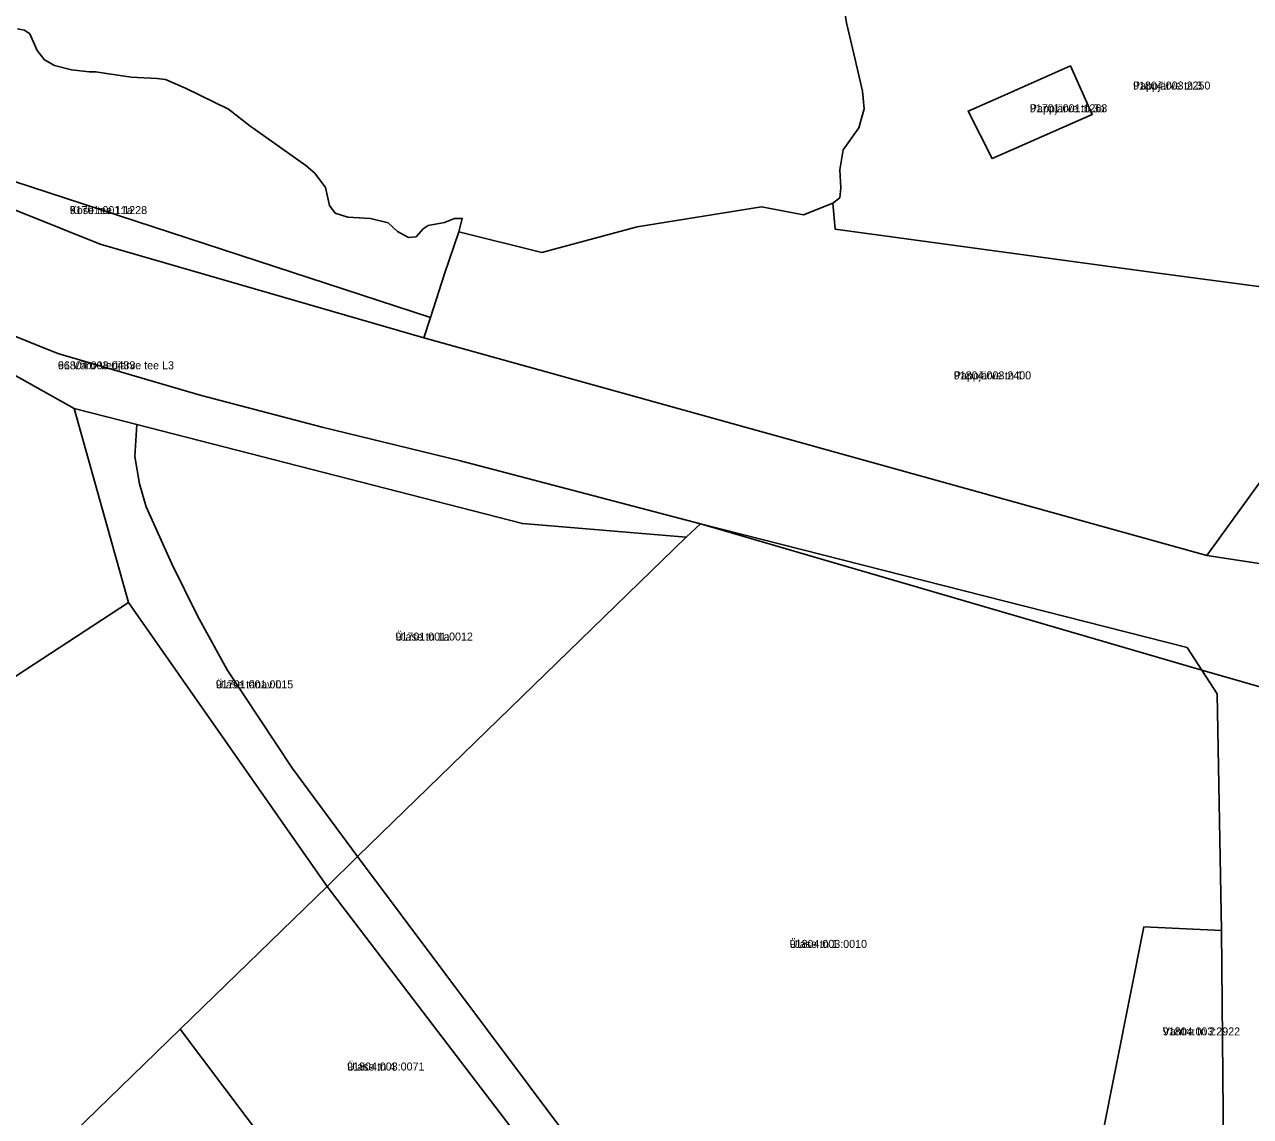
# Model space of a CAD drawing. Extents: x 655954 to 711923, y 6395079 to 6429745.
# Drawn here: x 680115.5 to 680345.2, y 6412086.7 to 6412291.4 of the extents above; entities that cross this region are included whole.
import ezdxf

# ---------------------------------------------------------------- set-up
doc = ezdxf.new("R2010")
doc.units = 0
for name, color, linetype in [('L_AADRESS', 7, 'Continuous'), ('PIIR', 7, 'Continuous'), ('TUNNUS', 7, 'Continuous')]:
    doc.layers.add(name, color=color, linetype=linetype)

msp = doc.modelspace()

# ---------------------------------------------------------------- linework, layer by layer
at = {"layer": 'PIIR'}
for points in [[(680270.91, 6412285.97), (680269.56, 6412291.77), (680268.21, 6412300.15), (680272.04, 6412300.46), (680309.99, 6412309.75), (680357.48, 6412321.49), (680370.12, 6412288.02), (680379.49, 6412257.67), (680371.24, 6412239.08), (680328.42, 6412244.77), (680267.41, 6412253.09), (680266.95, 6412257.92), (680268.29, 6412258.95), (680268.5, 6412260.8), (680268.26, 6412264.21), (680268.94, 6412267.94), (680271.87, 6412272.08), (680272.87, 6412275.64), (680272.53, 6412278.95)], [(680311.51, 6412283.68), (680296.9, 6412277.22), (680292.32, 6412275.21), (680296.81, 6412266.3), (680301.38, 6412268.31), (680315.56, 6412274.55)], [(680301.38, 6412268.31), (680296.81, 6412266.3), (680292.32, 6412275.21), (680296.9, 6412277.22), (680311.51, 6412283.68), (680315.56, 6412274.55)], [(680191.57, 6412236.5), (680190.32, 6412232.69), (680129.68, 6412250.27), (680106.42, 6412259.59), (680061.38, 6412279.1)], [(680057.47, 6412258.31), (680098.7, 6412238.99), (680121.74, 6412229.75), (680148.41, 6412221.98), (680171.26, 6412215.95), (680196.94, 6412209.71), (680242.17, 6412197.84), (680239.51, 6412195.3), (680208.82, 6412197.87), (680136.58, 6412216.43), (680124.79, 6412219.45), (680094.21, 6412236.6), (680073.54, 6412243.96), (680059.62, 6412250.38), (680048.66, 6412251.49)], [(680266.95, 6412257.92), (680267.41, 6412253.09), (680328.42, 6412244.77), (680371.24, 6412239.08), (680337.05, 6412191.89), (680190.32, 6412232.69), (680191.57, 6412236.5), (680194.23, 6412244.67), (680196.86, 6412252.6), (680212.46, 6412248.67), (680230.28, 6412253.54), (680253.6, 6412257.24), (680261.5, 6412255.76)], [(680029.07, 6412236.31), (680048.66, 6412251.49), (680059.62, 6412250.38), (680073.54, 6412243.96), (680094.21, 6412236.6), (680124.79, 6412219.45), (680135.01, 6412183.06), (680113.87, 6412169.29), (680093.78, 6412171.48), (680064.98, 6412158.77), (680062.91, 6412162.64), (680053.42, 6412181.06)], [(680135.01, 6412183.06), (680124.79, 6412219.45), (680136.58, 6412216.43), (680136.18, 6412210.48), (680137.05, 6412205.33), (680138.32, 6412201.02), (680143.13, 6412190.34), (680147.92, 6412180.6), (680153.46, 6412170.43), (680165.75, 6412151.95), (680177.93, 6412135.44), (680172.23, 6412129.84)], [(680136.18, 6412210.48), (680136.58, 6412216.43), (680208.82, 6412197.87), (680239.51, 6412195.3), (680177.93, 6412135.44), (680165.75, 6412151.95), (680153.46, 6412170.43), (680147.92, 6412180.6), (680143.13, 6412190.34), (680138.32, 6412201.02), (680137.05, 6412205.33)], [(680339.82, 6412121.56), (680325.23, 6412122.25), (680317.41, 6412082.68), (680305.27, 6412069.8), (680258.89, 6412067.74), (680264.48, 6412045.39), (680249.85, 6412039.28), (680177.93, 6412135.44), (680239.51, 6412195.3), (680242.17, 6412197.84), (680333.36, 6412174.63), (680338.98, 6412165.98)], [(680113.87, 6412169.29), (680135.01, 6412183.06), (680172.23, 6412129.84), (680144.65, 6412103.09), (680064.61, 6412025.27), (680029.16, 6412146.93), (680058.94, 6412160.44), (680062.91, 6412162.64), (680064.98, 6412158.77), (680093.78, 6412171.48)], [(680172.23, 6412129.84), (680207.25, 6412083.9), (680187.81, 6412068.25), (680179.6, 6412065.22), (680174.78, 6412065.85), (680169.78, 6412069.7), (680144.65, 6412103.09)], [(680325.23, 6412122.25), (680339.82, 6412121.56), (680340.18, 6412080.79), (680317.41, 6412082.68)], [(680144.65, 6412103.09), (680169.78, 6412069.7), (680174.78, 6412065.85), (680179.6, 6412065.22), (680187.81, 6412068.25), (680207.25, 6412083.9), (680216.28, 6412071.48), (680204.78, 6412056.18), (680218.04, 6412026.59), (680239.92, 6411995.28), (680256.59, 6412011.64), (680268.49, 6412001.99), (680151.27, 6411895.77), (680144.01, 6411889.12), (680137, 6411900.49), (680128.05, 6411895.16), (680136.21, 6411882.06), (680114.51, 6411862.4), (680110.62, 6411858.88), (680064.61, 6412025.27)]]:
    msp.add_lwpolyline(points, close=True, dxfattribs=at)
for points in [[(680372.55, 6412294.06), (680377.69, 6412279.06), (680382.91, 6412264.69), (680386, 6412255.23), (680385.97, 6412250.53), (680379.93, 6412239.55), (680347.28, 6412190.34), (680337.05, 6412191.89), (680371.24, 6412239.08), (680379.49, 6412257.67), (680370.12, 6412288.02), (680357.48, 6412321.49)], [(680269.56, 6412291.77), (680270.91, 6412285.97), (680272.53, 6412278.95), (680272.87, 6412275.64), (680271.87, 6412272.08), (680268.94, 6412267.94), (680268.26, 6412264.21), (680268.5, 6412260.8), (680268.29, 6412258.95), (680266.95, 6412257.92), (680261.5, 6412255.76), (680253.6, 6412257.24), (680230.28, 6412253.54), (680212.46, 6412248.67), (680196.86, 6412252.6), (680197.53, 6412255.1), (680196.1, 6412255.05), (680194.18, 6412254.32), (680191.13, 6412253.79), (680190.18, 6412253.13), (680188.87, 6412251.66), (680187.46, 6412251.48), (680185.38, 6412252.65), (680183.62, 6412254.24), (680180.34, 6412255.06), (680176.08, 6412255.32), (680173.72, 6412256.1), (680172.66, 6412257.51), (680171.93, 6412260.9), (680169.89, 6412263.55), (680168.24, 6412265), (680157.74, 6412272.45), (680153.73, 6412275.58), (680145.64, 6412279.51), (680141.95, 6412281.14), (680140.28, 6412281.29), (680135.48, 6412281.57), (680128.81, 6412282.6), (680127.62, 6412282.57), (680124.33, 6412282.96), (680121.15, 6412283.75), (680119.24, 6412284.83), (680117.9, 6412286.54), (680116.51, 6412289.67), (680115.52, 6412290.38), (680114.17, 6412290.66)], [(680114.17, 6412290.66), (680115.52, 6412290.38), (680116.51, 6412289.67), (680117.9, 6412286.54), (680119.24, 6412284.83), (680121.15, 6412283.75), (680124.33, 6412282.96), (680127.62, 6412282.57), (680128.81, 6412282.6), (680135.48, 6412281.57), (680140.28, 6412281.29), (680141.95, 6412281.14), (680145.64, 6412279.51), (680153.73, 6412275.58), (680157.74, 6412272.45), (680168.24, 6412265), (680169.89, 6412263.55), (680171.93, 6412260.9), (680172.66, 6412257.51), (680173.72, 6412256.1), (680176.08, 6412255.32), (680180.34, 6412255.06), (680183.62, 6412254.24), (680185.38, 6412252.65), (680187.46, 6412251.48), (680188.87, 6412251.66), (680190.18, 6412253.13), (680191.13, 6412253.79), (680194.18, 6412254.32), (680196.1, 6412255.05), (680197.53, 6412255.1), (680196.86, 6412252.6), (680194.23, 6412244.67), (680191.57, 6412236.5), (680061.38, 6412279.1)], [(680106.42, 6412259.59), (680129.68, 6412250.27), (680190.32, 6412232.69), (680337.05, 6412191.89), (680347.28, 6412190.34)], [(680705.81, 6412074.78), (680677.03, 6412081.28), (680624.53, 6412094.76), (680560.78, 6412111.23), (680546.23, 6412115.07), (680492.93, 6412129.05), (680406.11, 6412151.85), (680402.06, 6412153.11), (680351.83, 6412165.88), (680336.14, 6412170.36), (680242.17, 6412197.84), (680196.94, 6412209.71), (680171.26, 6412215.95), (680148.41, 6412221.98), (680121.74, 6412229.75), (680098.7, 6412238.99)], [(680340.18, 6412080.79), (680339.82, 6412121.56), (680338.98, 6412165.98), (680336.14, 6412170.36), (680351.83, 6412165.88), (680347.79, 6412147.37), (680349.36, 6412087.58), (680403.59, 6412086.99), (680403.88, 6412116.18), (680402.06, 6412153.11), (680406.11, 6412151.85), (680407.08, 6412132.37), (680407.88, 6412116.26), (680408.14, 6412056.92)], [(680207.25, 6412083.9), (680172.23, 6412129.84), (680177.93, 6412135.44), (680249.85, 6412039.28)]]:
    msp.add_lwpolyline(points, dxfattribs=at)

# ---------------------------------------------------------------- texts
at = {"layer": 'L_AADRESS'}
for s, p in [('Pappjärve tn 3', (680323.22, 6412279.25)), ('Pappjärve tn 3a', (680303.9, 6412274.99)), ('Kose tee 11a', (680123.97, 6412255.9)), ('66 Võru-Verijärve tee L3', (680121.76, 6412226.8)), ('Pappjärve tn 1', (680289.64, 6412224.91)), ('Ülase tn 1a', (680185.02, 6412175.94)), ('Ülase tänav L1', (680151.36, 6412166.98)), ('Ülase tn 1', (680258.88, 6412118.32)), ('Vahtra tn 2', (680328.79, 6412101.91)), ('Ülase tn 4', (680175.95, 6412095.33))]:
    msp.add_text(s, height=1.5, dxfattribs=at).set_placement(p)
at = {"layer": 'TUNNUS'}
for s, p in [('91804:003:2250', (680323.22, 6412279.25)), ('91701:001:1263', (680303.9, 6412274.99)), ('91701:001:1228', (680123.97, 6412255.9)), ('91804:003:0433', (680121.76, 6412226.8)), ('91804:003:2400', (680289.64, 6412224.91)), ('91701:001:0012', (680185.02, 6412175.94)), ('91701:001:0015', (680151.36, 6412166.98)), ('91804:003:0010', (680258.88, 6412118.32)), ('91804:003:2922', (680328.79, 6412101.91)), ('91804:003:0071', (680175.95, 6412095.33))]:
    msp.add_text(s, height=1.5, dxfattribs=at).set_placement(p)

doc.saveas('drawing.dxf')
